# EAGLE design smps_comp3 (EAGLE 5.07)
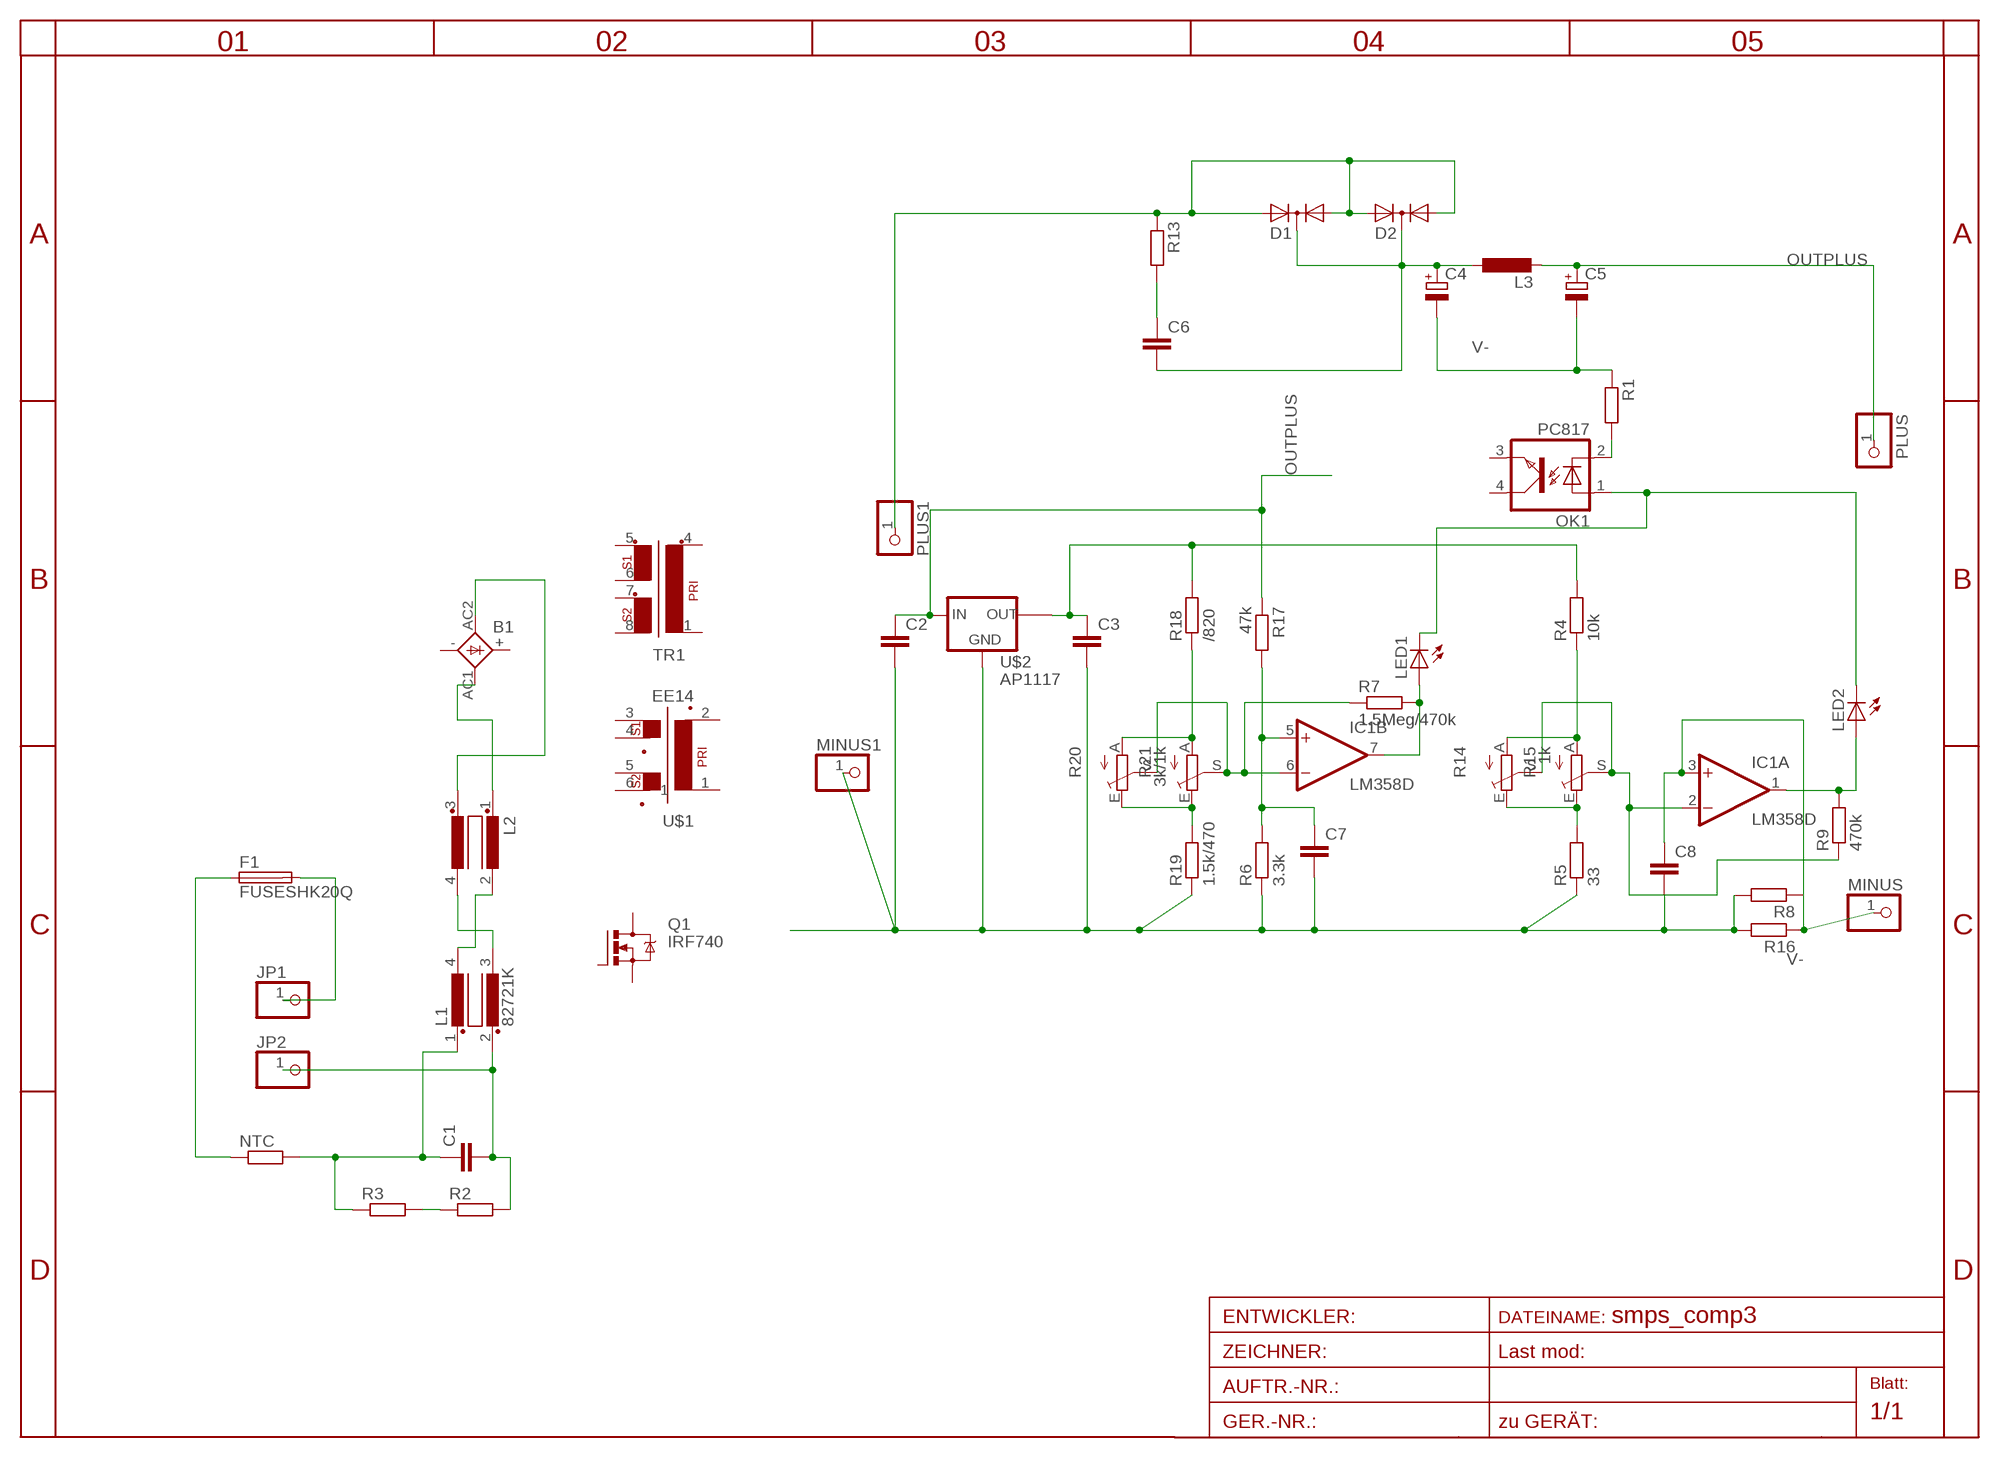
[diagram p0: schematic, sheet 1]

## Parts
B1  KBL  [KBL]
C1  C-EU150-084X183  [C150-084X183]
C2  C-EUC1206  [C1206]
C3  C-EUC1206  [C1206]
C4  CPOL-EUE5-8.5  [E5-8,5]
C5  CPOL-EUE5-8.5  [E5-8,5]
C6  C-EUC0805  [C0805]
C7  C-EUC0805  [C0805]
C8  C-EUC0805  [C0805]
D1  DIODE-2AC|CAIW220V  [IW220ABS]
D2  DIODE-2AC|CAIW220V  [IW220ABS]
F1  FUSESHK20Q  [SHK20Q]
IC1  LM358D  [SO08]
JP1  PINHD-1X12MM2  [1X2MM2]
JP2  PINHD-1X12MM2  [1X2MM2]
L1  82721K  [82721K]
L2  R1405VB1  [B1]
L3  L-EU0207/12  [0207/12]
LED1  LED3MM  [LED3MM]
LED2  LED3MM  [LED3MM]
MINUS  PINHD-1X12MM2  [1X2MM2]
MINUS1  PINHD-1X11X0.4  [1X01]
NTC  R-EU_0204/7  [0204/7]
OK1  PC817  [DIL04]
PLUS  PINHD-1X12MM2  [1X2MM2]
PLUS1  PINHD-1X11X0.4  [1X01]
Q1  IRF740  [TO220BV]
R1  R-EU_R0805  [R0805]
R2  R-EU_R1206  [R1206]
R3  R-EU_R1206  [R1206]
R4  10k  R-EU_R0805  [R0805]
R5  33  R-EU_R0805  [R0805]
R6  3.3k  R-EU_R0805  [R0805]
R7  1.5Meg/470k  R-EU_R0805  [R0805]
R8  R-EU_R2010  [R2010]
R9  470k  R-EU_R0805  [R0805]
R13  R-EU_R0805  [R0805]
R14  TRIM_EU-S64W  [S64W]
R15  1k  TRIM_EU-CA6V  [CA6V]
R16  R-EU_R2010  [R2010]
R17  47k  R-EU_R0805  [R0805]
R18  /820  R-EU_R0805  [R0805]
R19  1.5k/470  R-EU_R0805  [R0805]
R20  TRIM_EU-S64W  [S64W]
R21  3k/1k  TRIM_EU-CA6V  [CA6V]
TR1  EE20-2  [EE20-2]
U$1  EE14  [EE14]
U$2  AP1117  [SOT223]

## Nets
A: R4.1 R14.A R15.A
A1: R18.1 R20.A R21.A
CPLUS: C4.+ C6.2 D1.C D2.C L3.1
E: R5.2 R14.E R15.E
E1: R19.2 R20.E R21.E
N$1: C1.2 JP2.1 L1.2 R2.2
N$2: C1.1 L1.1 NTC.2 R3.1
N$3: F1.2A JP1.1
N$4: IC1.7(B:OUT) LED1.A R7.2
N$5: L1.4 L2.2
N$6: R2.1 R3.2
N$7: B1.AC2(AC1) L2.3
N$8: B1.AC1(AC2) L2.1
N$9: F1.1A NTC.1
N$10: IC1.6(B:-IN) R7.1 R21.S
N$11: IC1.1(A:OUT) LED2.A R9.2
N$12: OK1.2(C) R1.2
N$13: LED1.K(C) LED2.K(C) OK1.1(A)
N$14: L1.3 L2.4
N$16: C7.1 IC1.5(B:+IN) R6.2 R17.2
N$27: C6.1 R13.2
OUT: C8.1 IC1.3(A:+IN) MINUS.1 R8.1 R16.1
OUTPLUS: C2.1 C5.+ L3.2 PLUS.1 R17.1 U$2.3(IN)
S: IC1.2(A:-IN) R9.1 R14.S R15.S
S1: R20.S
TPLUS: D1.A1 D1.A2 D2.A1 D2.A2 PLUS1.1 R13.1
V+: C3.1 R4.2 R18.2 U$2.4(TAB)
V-: C2.2 C3.2 C4.- C5.- C7.2 C8.2 MINUS1.1 R1.1 R5.1 R6.1 R8.2 R16.2 R19.1 U$2.1(GND)
Unconnected: B1.+ B1.- OK1.3(EMIT) OK1.4(COL) Q1.D Q1.G Q1.S TR1.1 TR1.4 TR1.5 TR1.6 TR1.7 TR1.8 U$1.1 U$1.2 U$1.3 U$1.4 U$1.5 U$1.6 U$2.2(OUT)

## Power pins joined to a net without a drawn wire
V+: IC1.8(P:V+)
V-: IC1.4(P:V-)

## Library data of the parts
B1 = rectifier:KBL: DIOTEC RECTIFIER
C1-C3 C6-C8 = rcl:C-EU: CAPACITOR, European symbol
C4 C5 = rcl:CPOL-EU: POLARIZED CAPACITOR, European symbol
D1 D2 = diode:DIODE-2AC|CA: Dual DIODE Anode-Cathode|Cathode-Anode
F1 = fuse:FUSE: Fuse
IC1 = linear:LM358: OP AMP also LM158; LM258; LM2904 Source: http://cache.national.com/ds/LM/LM158.pdf
JP1 JP2 MINUS MINUS1 PLUS PLUS1 = pinhead:PINHD-1X1: PIN HEADER
L1 = inductors:82721K: FILTER
L2 = inductor-nkl:R1405V: Übertrager (verlustarm) bis typ. 400kHz Power transformer (low loss) up to typ. 400kHz
L3 = rcl:L-EU: INDUCTOR, European symbol
LED1 LED2 = led:LED: LED
NTC R1-R9 R13 R16-R19 = rcl:R-EU_: RESISTOR, European symbol
OK1 = optocoupler:PC817: SHARP OPTO COUPLER
Q1 = transistor-power:IRF740: N-CHANNEL MOS FET
R14 R15 R20 R21 = pot:TRIM_EU-: POTENTIOMETER
TR1 = trafo:EE20-2: TRANSFORMER 1 primary winding, 2 secondary windings ERA
U$1 = trafo:EE14
U$2 = v-reg:AP1117

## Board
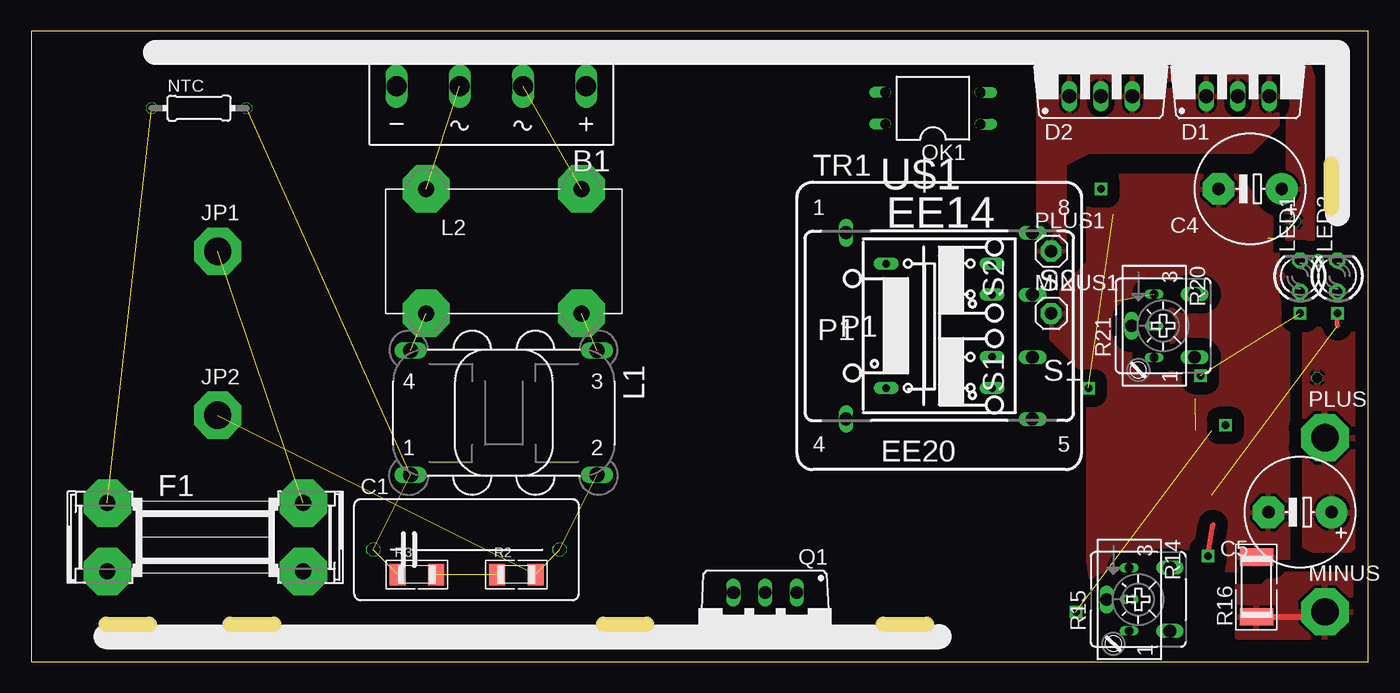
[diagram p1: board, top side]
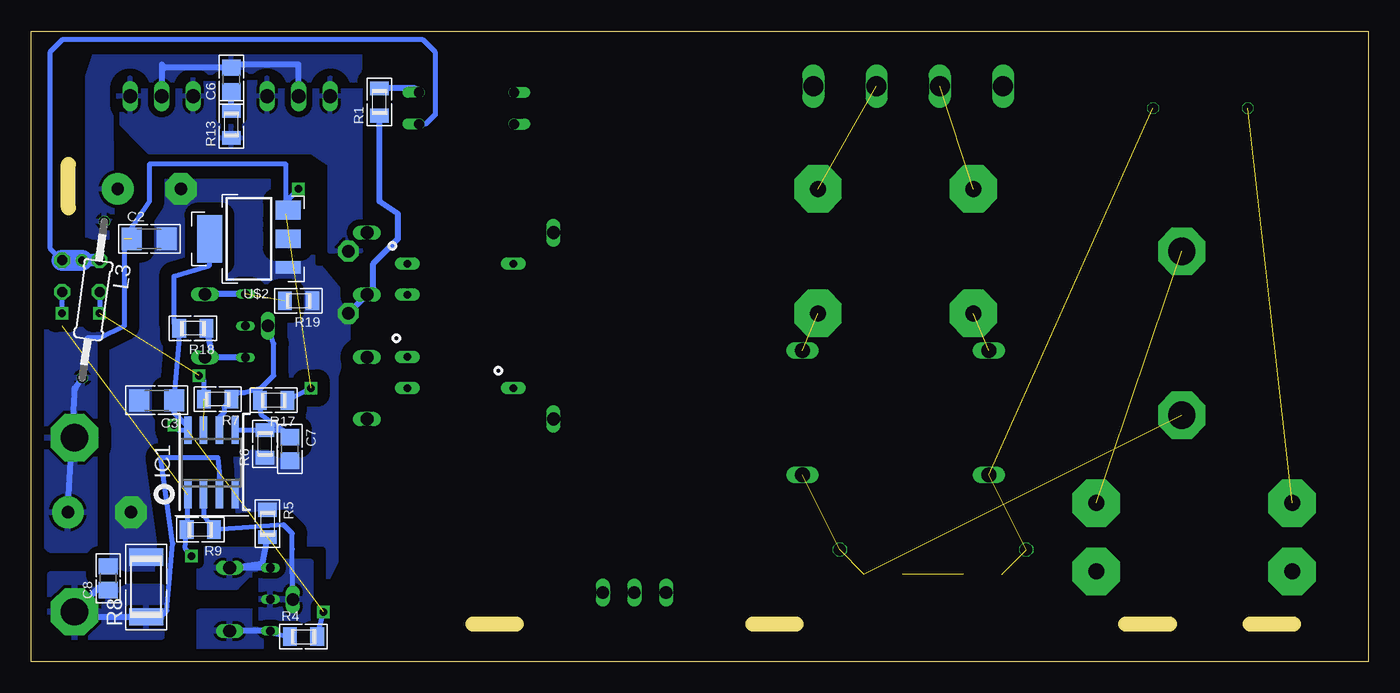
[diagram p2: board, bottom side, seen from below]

Size 107.5 x 50.7 mm. Coordinates in mm from the lower left corner, seen from the top.
Outline: 0,0 107.5,0 107.5,50.7 0,50.7 0,0
Copper layers (1*16): Top 0.035mm / dielectric 1.5mm / Bottom 0.035mm
Design rules "default": minimum track width 10mil, minimum drill 20mil, track to track 8mil, track to pad 8mil, pad to pad 8mil, via to via 8mil, smd to smd 8mil, copper to edge 40mil, drill to drill 8mil, minimum pad ring 1mil, minimum via ring 8mil, stop-mask expansion 4mil, vias tented up to drill 0mil, thermal gap 10mil
Milling: 5 lines

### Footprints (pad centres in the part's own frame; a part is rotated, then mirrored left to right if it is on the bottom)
KBL = drill 1.6 long: + -7.62,-1.27; - 7.62,-1.27; AC1 2.54,-1.27; AC2 -2.54,-1.27
C150-084X183 = drill 1.016 octagon: 1 -7.493,0; 2 7.493,0
C1206 = smd 1.6 x 1.8: 1 -1.4,0; 2 1.4,0
E5-8,5 = drill 1 pad 2.54 round: + -2.54,0 | drill 1 pad 2.54 octagon: - 2.54,0
C0805 = smd 1.3 x 1.5: 1 -0.95,0; 2 0.95,0
IW220ABS = drill 1.118 long: A1 -2.54,-2.54; A2 2.54,-2.54; C 0,-2.54
SHK20Q = drill 1.3 pad 3.81 octagon: 1A -7.874,2.75; 1B -7.874,-2.75; 2A 7.874,2.75; 2B 7.874,-2.75
SO08 = smd 0.6 x 2.2: 1 -1.905,-2.6; 2 -0.635,-2.6; 3 0.635,-2.6; 4 1.905,-2.6; 5 1.905,2.6; 6 0.635,2.6; 7 -0.635,2.6; 8 -1.905,2.6
1X2MM2 = drill 2.2 pad 3.81 octagon: 1 0,0
82721K = drill 1.194 long: 1 7.493,5.004; 2 -7.493,5.004; 3 -7.493,-5.004; 4 7.493,-5.004
B1 = drill 1.27 pad 3.81 octagon: 1 -6.25,5; 2 -6.25,-5; 3 6.25,5; 4 6.25,-5
0207/12 = drill 0.813 octagon: 1 -6.35,0; 2 6.35,0
LED3MM = drill 0.8 pad 1.27 octagon: A -1.27,0; K 1.27,0
1X01 = drill 1 pad 1.676 octagon: 1 0,0
0204/7 = drill 0.813 octagon: 1 -3.81,0; 2 3.81,0
DIL04 = drill 0.813 offset: 1 -1.27,-3.81; 2 1.27,-3.81; 3 1.27,3.81; 4 -1.27,3.81
TO220BV = drill 1.016 long: D 0,-2.54; G -2.54,-2.54; S 2.54,-2.54
R0805 = smd 1.1 x 1.5: 1 -1.1,0; 2 1.1,0
R1206 = smd 1.3 x 1.7: 1 -1.55,0; 2 1.55,0
R2010 = smd 1.4 x 2.7: 1 -2.4,0; 2 2.4,0
S64W = drill 0.7 long: A 2.54,1.27; E -2.54,1.27; S 0,1.27
CA6V = drill 1.016 long: A -2.54,-2.54; E 2.54,-2.54; S 0,2.54
EE20-2 = drill 1.016 long: 1 -7.493,7.493; 4 -7.493,-7.493; 5 7.493,-7.493; 6 7.493,-2.515; 7 7.493,2.515; 8 7.493,7.493
EE14 = drill 0.6 pad 1 long: 1 4.25,-5; 2 4.25,5; 3 -4.25,5 | drill 0.6 pad 1.016 long: 4 -4.25,2.5; 5 -4.25,-2.5; 6 -4.25,-5
SOT223 = smd 1 x 2: 1 -2.3,-3.15 | smd 1.5 x 2: 2 0,-3.15; 3 2.3,-3.15 | smd 3.8 x 2: 4 0,3.15

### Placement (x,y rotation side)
B1  37,45 180 top
C1  35,9 0 top
C2  98,34 0 bottom
C3  97.4,21 180 bottom
C4  98,38 180 top
C5  102,12 180 top
C6  91.4,46.8 90 bottom
C7  86.7,17.1 270 bottom
C8  101.3,6.7 90 bottom
D1  97,48 0 top
D2  86,48 0 top
F1  14,10 0 top
IC1  93,16 0 bottom
JP1  15,33 0 top
JP2  15,19.8 0 top
L1  38,20 180 top
L2  38,33 0 top
L3  102.5,29.1 262 bottom
LED1  102,31 90 top
LED2  105,31 90 top
MINUS  104,4 0 top
MINUS1  82,28 0 top
NTC  13.5,44.5 0 top
OK1  72.5,44.5 90 top
PLUS  104,18 0 top
PLUS1  82,33 0 top
Q1  59,3 180 top
R1  79.5,45 90 bottom
R2  39,7 0 top
R3  31,7 0 top
R4  85.6,2 0 bottom
R5  88.5,11.1 270 bottom
R6  88.7,17.5 90 bottom
R7  92.5,21.1 180 bottom
R8  98.25,6 90 bottom
R9  93.9,10.6 180 bottom
R13  91.4,43.2 90 bottom
R14  87,5 270 top
R15  89,5 90 top
R16  98.5,6 90 top
R17  88,21 180 bottom
R18  94.5,26.8 180 bottom
R19  86,29 180 bottom
R20  89,27 270 top
R21  91,27 90 top
TR1  73,27 0 top
U$1  73,27 180 top
U$2  90,34 90 bottom

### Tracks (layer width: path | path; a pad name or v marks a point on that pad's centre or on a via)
A
  Bottom 0.4: R4.1 88.11,2.3 R14.A
  Bottom 0.5: R14.A R15.A
  pour Bottom (isolate 0.5, rank 2): 89,4 94,4 94,1 89,1
A1
  Bottom 0.5: 92.86,24.46 R21.A | R20.A 92.86,24.46 | 92.86,24.46 R18.1
CPLUS
  Bottom 0.5: D2.C 86,48 91.15,48 C6.2 96.75,47.75 97,48 D1.C
  pour Bottom (isolate 1): 81,50 102,50 103,47 103,34 101,34 101,37 101.1,46.8 81.1,46.8
  pour Top (isolate 1): 81,50 102,50 103,47 103,34 101,34 101,37 101.1,46.8 81.1,46.8
E
  Bottom 0.5: R5.2 88.9,7.9 R15.E R14.E
  pour Bottom (isolate 0.5, rank 2): 90,7 89,7 89,9 94,9 94,6 91,6
E1  (1 unrouted)
  Bottom 0.5: R20.E R21.E
N$1  (3 unrouted)
N$2  (3 unrouted)
N$3  (1 unrouted)
N$4  (via drill 0.6)  (2 unrouted)
  Bottom 0.4: R7.2 93.6,22.6 v94,23 | LED1.A v102,28
N$5  (1 unrouted)
N$6  (1 unrouted)
N$7  (1 unrouted)
N$8  (1 unrouted)
N$9  (1 unrouted)
N$10
  Bottom 0.4: R21.S 88,25.54 88,23 89,22 90.36,21.64 90.86,21.64 R7.1 92,20.5 92,20 92.36,19.64 IC1.6
N$11  (via drill 0.6)  (1 unrouted)
  Top 0.4: 105,27 v105,28 | v94.6,8.5 95,11
  Bottom 0.4: v105,28 LED2.A | v94.6,8.5 95.1,9.1 R9.2 94.91,11.2 IC1.1
N$12
  Bottom 0.5: R1.2 76.64,46.1 OK1.2
N$13  (via drill 0.6)
  Bottom 0.4: OK1.1 75.77,43.23 75,44 75,49 76,50 105,50 106,49 106,33.27 LED2.K
  Bottom 1: v103.4,32.27 LED1.K
  Bottom 1.676: LED2.K v103.4,32.27
N$14  (1 unrouted)
N$16
  Bottom 0.4: IC1.5 R6.2 87.25,18.6 | C7.1 87.25,18.6 | R17.2 89,19.85 87.25,18.6
N$27
  Bottom 0.5: R13.2 C6.1
OUT
  Top 0.5: R16.1 103.6,3.6 MINUS.1 | R16.1 98.8,3.6 | 98,4 99.6,4 R16.1
  Bottom 0.4: IC1.3 92.36,15.27 92.5,16.4 97.1,16.4 96.1,9.5 96.6,4.1 97,3.7 98.15,3.7 R8.1
  Bottom 0.5: C8.1 101.25,5.75 101,6 102,6 MINUS.1 103.6,3.6 R8.1
  pour Bottom (isolate 1.016, rank 3): 102,6 103,7 106,7 106,2 97,2 97,6
  pour Top (isolate 1.016, rank 3): 100,7 106,7 106,2 97,2 97,6 99,6
OUTPLUS  (via drill 0.6)  (2 unrouted)
  Bottom 0.4: U$2.3 86.85,36.15 87,36 87,37 v86,38 | v85,22 R17.1
  Bottom 0.406: 103,26 102,26 100,27 100,34 98,37 98,40 87,40 87,36.3 U$2.3
  Bottom 0.5: L3.2 103.95,21.95 104,22 104,21.54 C5.+
  pour Bottom (isolate 1, rank 5): 107,28 107,10 106,9 103,9 101,10 101,28
  pour Top (isolate 1, rank 5): 107,28 107,10 106,9 103,9 101,10 101,28
S
  Bottom 0.4: IC1.2 93.6,13.4 93.6,11.7 R9.1 87.2,11 86.5,10.3 86.5,9.04 R15.S
  pour Bottom (isolate 0.5): 85,8 89,8 89,2 85,2
TPLUS
  pour Bottom (isolate 0.5, rank 2): 81,33 81,46 82,47 100,47 101,46 101,44 98,41 85,41 83.5,40 83.5,33
  pour Top (isolate 0.5, rank 2): 81,33 81,46 82,47 100,47 101,46 101,44 98,41 85,41 83,40 83,33
V+  (via drill 0.6)  (1 unrouted)
  Bottom 0.4: U$2.4 93.15,31.85 96,31 96,27.2 R18.2 95.6,25.6 C3.1 96,20 95,19 95,18.7 IC1.8 95.6,18.6 v96,19 | R4.2 v84,4
V-
  Bottom 0.5: R1.1 79.5,37 78,36 78,34 80,32 80,30 MINUS1.1
  pour Bottom (isolate 1, rank 4, no thermals): 97,40 86,40 84.5,38 84.5,32 82,29 82,26 83,23 83,8 86,2 101,2 101,34
  pour Top (isolate 1, rank 4): 97,39 86,39 85,38 85,32 82,29 82,26 85,23 85,8 86,2 101,2 101,5 101,34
